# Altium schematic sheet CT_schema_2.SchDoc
size 372 x 328 mm
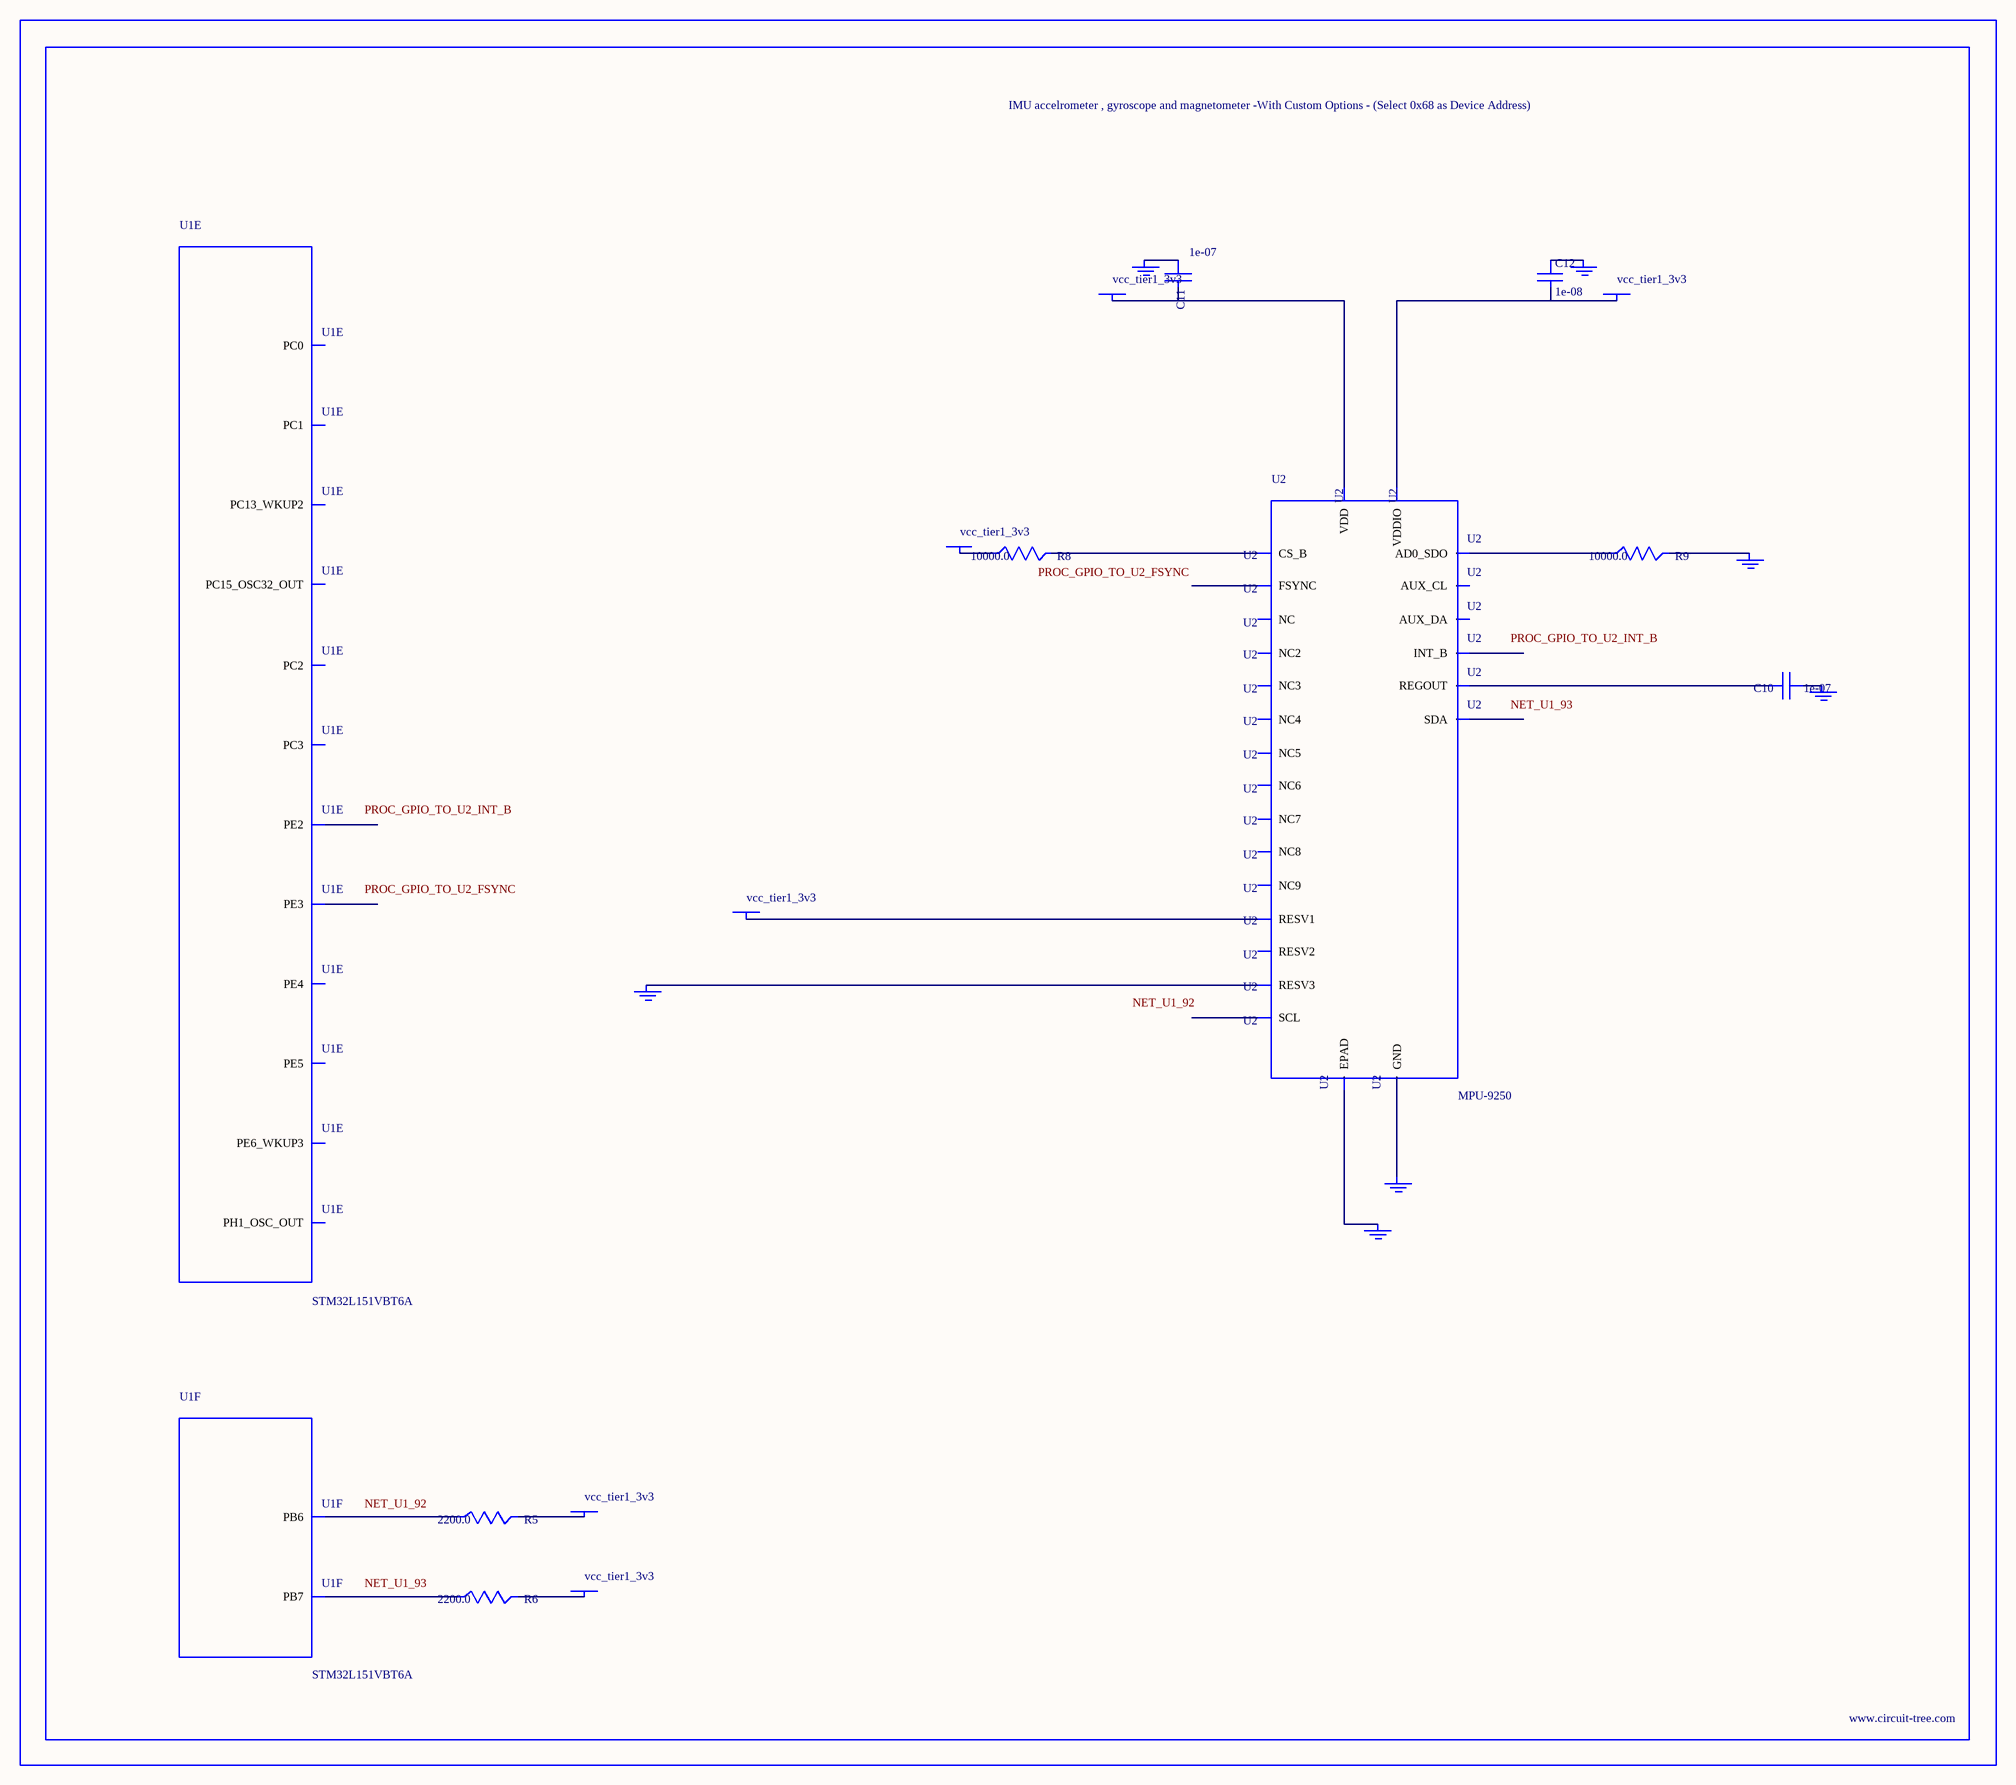
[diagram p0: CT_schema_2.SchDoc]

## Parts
BORDER1  (no value)
C10  1e-07  [C0402]
C11  1e-07  [C0402]
C12  1e-08  [C0402]
GND_INSTANCE_1_0  (no value)
GND_INSTANCE_1_1  (no value)
GND_INSTANCE_1_2  (no value)
GND_INSTANCE_1_3  (no value)
GND_INSTANCE_1_4  (no value)
GND_INSTANCE_1_5  (no value)
GND_INSTANCE_1_6  (no value)
POWER_INSTANCE_1_0  vcc_tier1_3v3
POWER_INSTANCE_1_1  vcc_tier1_3v3
POWER_INSTANCE_1_2  vcc_tier1_3v3
POWER_INSTANCE_1_3  vcc_tier1_3v3
POWER_INSTANCE_1_4  vcc_tier1_3v3
POWER_INSTANCE_1_5  vcc_tier1_3v3
R5  2200.0  [R0603]
R6  2200.0  [R0603]
R8  10000.0  [R0603]
R9  10000.0  [R0603]
U1  STM32L151VBT6A  [LQFP100]  (parts E,F of 8)
U2  MPU-9250  [QFN24_2]

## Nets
NetC10_1: C10.1 GND_INSTANCE_1_2.0(GND)
NetC10_2: C10.2 U2.10(REGOUT)
NetC11_1: C11.1 GND_INSTANCE_1_3.0(GND)
NetC11_2: C11.2 POWER_INSTANCE_1_2.0(PWR) U2.13(VDD)
NetC12_1: C12.1 GND_INSTANCE_1_0.0(GND)
NetC12_2: C12.2 POWER_INSTANCE_1_1.0(PWR) U2.8(VDDIO)
NetGND_INSTANCE_1_1_0: GND_INSTANCE_1_1.0(GND) R9.2
NetGND_INSTANCE_1_4_0: GND_INSTANCE_1_4.0(GND) U2.20(RESV3)
NetGND_INSTANCE_1_5_0: GND_INSTANCE_1_5.0(GND) U2.25(EPAD)
NetGND_INSTANCE_1_6_0: GND_INSTANCE_1_6.0(GND) U2.18(GND)
NetPOWER_INSTANCE_1_0_0: POWER_INSTANCE_1_0.0(PWR) U2.1(RESV1)
NetPOWER_INSTANCE_1_3_0: POWER_INSTANCE_1_3.0(PWR) R8.1
NetPOWER_INSTANCE_1_4_0: POWER_INSTANCE_1_4.0(PWR) R5.2
NetPOWER_INSTANCE_1_5_0: POWER_INSTANCE_1_5.0(PWR) R6.2
NetR5_1: R5.1 U1.92(PB6)
NetR6_1: R6.1 U1.93(PB7)
NetR8_2: R8.2 U2.22(CS_B)
NetR9_1: R9.1 U2.9(AD0_SDO)

Not connected (* = marked no-connect by the designer): U1 1(PE2) 2(PE3) 3(PE4) 4(PE5) 5(PE6_WKUP3) 7(PC13_WKUP2) 9(PC15_OSC32_OUT) 13(PH1_OSC_OUT) 15(PC0) 16(PC1) 17(PC2) 18(PC3); U2 2(NC) 3(NC2) 4(NC3) 5(NC4) 6(NC5) 7(AUX_CL) 11(FSYNC) 12(INT_B) 14(NC6) 15(NC7) 16(NC8) 17(NC9) 19(RESV2) 21(AUX_DA) 23(SCL) 24(SDA)

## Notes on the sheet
- Labels drawn without touching a wire or pin: NET_U1_92, NET_U1_93, PROC_GPIO_TO_U2_FSYNC, PROC_GPIO_TO_U2_INT_B

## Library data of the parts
BORDER1 = BORDER_PAGE1
C10 C11 = C0402C104K3RACTU
C12 = C0402C103K3RAC
GND_INSTANCE_1_0-GND_INSTANCE_1_6 = GND
POWER_INSTANCE_1_0-POWER_INSTANCE_1_5 = PWR
R5 R6 = RC0603JR-072K2L
R8 R9 = RC0603JR-0710KL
